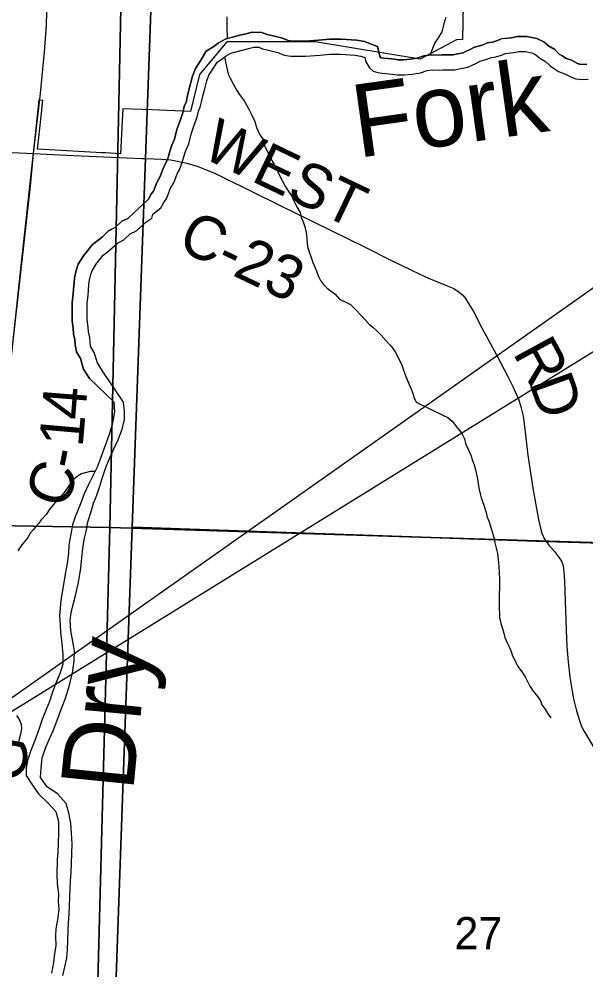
# Model space of a CAD drawing. Extents: x -7.5 to 26.5, y 3.5 to 25.5.
# Drawn here: x -2.386 to -1.65, y 20.587 to 21.822 of the extents above; entities that cross this region are included whole.
import ezdxf

# ---------------------------------------------------------------- set-up
doc = ezdxf.new("R2010")
doc.units = 0
for name, color, linetype in [('GM_X_Corporation', 7, 'Continuous'), ('GM_X_County_Road', 7, 'Continuous'), ('GM_X_County_Road_Text', 7, 'Continuous'), ('GM_X_Minor_River', 7, 'Continuous'), ('GM_X_Minor_River_Text', 7, 'Continuous'), ('GM_X_Section_Text', 7, 'Continuous'), ('GM_X_Township_Road_Text', 7, 'Continuous'), ('SH_Text', 7, 'Continuous')]:
    doc.layers.add(name, color=color, linetype=linetype)

msp = doc.modelspace()

# ---------------------------------------------------------------- linework, layer by layer
at = {"layer": 'GM_X_Corporation'}
for points in [[(-3.3166, 19.1895), (-2.696, 19.1768), (-2.693, 19.1768), (-2.3401, 19.1651), (-2.3128, 19.1642), (-2.2728, 20.2496), (-2.265, 20.4395), (-2.2643, 20.4572), (-2.2393, 21.1622), (-2.2218, 21.6412), (-2.2048, 22.1084), (-2.1854, 22.6407), (-2.1684, 23.1064), (-2.1683, 23.1094), (-2.1213, 24.4), (-5.1194, 24.4)], [(-2.1213, 24.4), (-2.1683, 23.1094), (-2.1684, 23.1064), (-2.1854, 22.6407), (-2.2048, 22.1084), (-2.2218, 21.6412), (-2.2393, 21.1622), (-1.7013, 21.1435), (-0.6673, 21.1123), (-0.2751, 21.1005), (-0.1918, 21.0972), (-0.1864, 21.0971), (-0.1806, 21.0967), (-0.0857, 21.093), (-0.0438, 21.0913), (0.0729, 21.0875), (0.2211, 21.0828)], [(-1.8079, 21.9086), (-1.8101, 21.7954), (-1.8178, 21.7951), (-1.8651, 21.77), (-2.0016, 21.7923), (-2.1161, 21.7923), (-2.1516, 21.75), (-2.1632, 21.702), (-2.2136, 21.7039), (-2.2515, 21.7053), (-2.2518, 21.6978), (-2.2541, 21.6471), (-2.2732, 21.6481), (-2.2793, 21.6484), (-2.2861, 21.6488), (-2.309, 21.65), (-2.3391, 21.6517), (-2.3623, 21.653), (-2.3601, 21.6718), (-2.357, 21.6995), (-2.3552, 21.716), (-2.3603, 21.7166), (-2.3679, 21.6477), (-2.3713, 21.6164), (-2.3726, 21.6044), (-2.3852, 21.4892), (-2.398, 21.3679)], [(0.2211, 21.0828), (0.0729, 21.0875), (-0.0438, 21.0913), (-0.0857, 21.093), (-0.1806, 21.0967), (-0.1864, 21.0971), (-0.1918, 21.0972), (-0.2751, 21.1005), (-0.6673, 21.1123), (-1.7013, 21.1435), (-2.2393, 21.1622), (-2.2643, 20.4572), (-2.265, 20.4395), (-2.2728, 20.2496), (-2.3128, 19.1642), (-2.3401, 19.1651), (-2.693, 19.1768), (-2.696, 19.1768), (-3.3166, 19.1895)]]:
    msp.add_lwpolyline(points, dxfattribs=at)
for points in [[(-3.2367, 22.18), (-2.2479, 22.1217), (-2.268, 21.1618), (-3.2602, 21.1789)], [(-2.2479, 22.1217), (-0.9461, 22.0601), (-0.9782, 21.2998), (-1.0267, 21.301), (-1.0307, 21.1237), (-1.2798, 21.1309), (-2.268, 21.1618)], [(-3.2602, 21.1789), (-2.268, 21.1618), (-2.2948, 20.1631), (-3.2852, 20.1896)], [(-2.268, 21.1618), (-1.2798, 21.1309), (-1.3089, 20.136), (-2.2948, 20.1631)]]:
    msp.add_lwpolyline(points, close=True, dxfattribs=at)
at = {"layer": 'GM_X_County_Road'}
msp.add_line((-2.4681, 21.6518), (-2.3675, 21.6474), dxfattribs=at)
for points in [[(-2.3675, 21.6474), (-2.3584, 21.7252), (-2.3531, 21.7795), (-2.3506, 21.814), (-2.3494, 21.849), (-2.3492, 21.857), (-2.3487, 21.8659), (-2.3479, 21.8755), (-2.3468, 21.8862), (-2.3416, 21.9409), (-2.3405, 21.9508), (-2.3396, 21.9573)], [(-2.5257, 20.8926), (-2.5079, 20.917), (-2.4963, 20.933), (-2.4804, 20.9556), (-2.4754, 20.9625), (-2.4713, 20.9696), (-2.4682, 20.9759), (-2.4643, 20.9845), (-2.4611, 20.9921), (-2.4572, 21.0064), (-2.4543, 21.0211), (-2.4508, 21.0481), (-2.4437, 21.0846), (-2.4394, 21.1065), (-2.4347, 21.1375), (-2.4159, 21.2518), (-2.4045, 21.3189), (-2.4008, 21.3419), (-2.3714, 21.6048), (-2.3675, 21.6474)], [(-2.3675, 21.6474), (-2.3155, 21.6446), (-2.2266, 21.6409)], [(-2.2266, 21.6409), (-2.2216, 21.6407), (-2.2012, 21.6401), (-2.1892, 21.6389), (-2.1801, 21.6374), (-2.1764, 21.6366)], [(-2.1764, 21.6366), (-2.168, 21.6347), (-2.1549, 21.6308), (-2.1419, 21.6259), (-2.1322, 21.6217), (-2.1214, 21.6167), (-2.0468, 21.5799), (-1.9363, 21.5255), (-1.9023, 21.5084), (-1.8763, 21.4957), (-1.8582, 21.4873), (-1.8488, 21.4831), (-1.8382, 21.479), (-1.8299, 21.4754), (-1.8212, 21.472), (-1.8145, 21.4674), (-1.8095, 21.4634), (-1.8059, 21.459)], [(-1.8059, 21.459), (-1.802, 21.4527), (-1.7958, 21.4422), (-1.7843, 21.42), (-1.7657, 21.3857), (-1.7505, 21.3569), (-1.7444, 21.3447), (-1.741, 21.3372), (-1.7373, 21.3289), (-1.7344, 21.3185), (-1.7313, 21.3062), (-1.7288, 21.2894), (-1.7251, 21.2556), (-1.7184, 21.213), (-1.7113, 21.1719), (-1.7087, 21.1607), (-1.7069, 21.1545), (-1.7038, 21.1474), (-1.701, 21.143), (-1.6977, 21.1386)], [(-1.6977, 21.1386), (-1.697, 21.1378), (-1.6905, 21.1305), (-1.6853, 21.1236), (-1.6814, 21.1178), (-1.6793, 21.1121), (-1.6783, 21.1035), (-1.6773, 21.0921), (-1.6755, 21.0282), (-1.6745, 21.0074), (-1.6729, 20.9871), (-1.6706, 20.9674), (-1.6677, 20.949), (-1.6658, 20.9393), (-1.6617, 20.9237), (-1.658, 20.9112), (-1.6552, 20.9032), (-1.6524, 20.8978), (-1.63, 20.8601)]]:
    msp.add_lwpolyline(points, dxfattribs=at)
at = {"layer": 'GM_X_Minor_River'}
for points in [[(-2.1151, 21.7966), (-2.1158, 21.8123), (-2.1156, 21.8191), (-2.1158, 21.8248)], [(-1.852, 21.7751), (-1.8462, 21.7899), (-1.841, 21.7977), (-1.8366, 21.8052), (-1.8341, 21.8138), (-1.8328, 21.8195), (-1.8311, 21.8243)], [(-1.7588, 21.7963), (-1.7657, 21.7936), (-1.7712, 21.792), (-1.7775, 21.7909), (-1.7845, 21.7881), (-1.7943, 21.7855), (-1.8009, 21.782), (-1.8059, 21.7798), (-1.8093, 21.7781), (-1.8184, 21.7765), (-1.8223, 21.7756), (-1.831, 21.7755), (-1.8362, 21.7753), (-1.8412, 21.7751), (-1.8501, 21.7754), (-1.8604, 21.774), (-1.8692, 21.7711), (-1.8781, 21.7696), (-1.8864, 21.7689), (-1.8936, 21.7688), (-1.8984, 21.7696), (-1.9072, 21.7706), (-1.9124, 21.7712), (-1.9159, 21.7715), (-1.916, 21.7716), (-1.9174, 21.7739), (-1.9205, 21.7864), (-1.9373, 21.7929), (-1.9474, 21.7943), (-1.9677, 21.7957), (-1.9833, 21.7958), (-1.9967, 21.7946), (-2.0146, 21.7933), (-2.0317, 21.7932), (-2.0363, 21.794), (-2.0439, 21.797), (-2.0559, 21.8), (-2.0639, 21.8018), (-2.0705, 21.8046), (-2.0835, 21.805), (-2.0912, 21.8029), (-2.0992, 21.8009), (-2.1183, 21.7958), (-2.1276, 21.7904), (-2.1345, 21.7854), (-2.1429, 21.78), (-2.1499, 21.7686), (-2.1568, 21.7579), (-2.1609, 21.7478), (-2.163, 21.7394), (-2.1642, 21.7347), (-2.1659, 21.7281), (-2.1683, 21.7185), (-2.1692, 21.7136), (-2.1715, 21.7086), (-2.1735, 21.7002), (-2.1765, 21.6916), (-2.1786, 21.6855), (-2.1813, 21.6784), (-2.1843, 21.6659), (-2.1877, 21.658), (-2.1897, 21.6516), (-2.1925, 21.6421), (-2.1955, 21.6346), (-2.1984, 21.6293), (-2.2028, 21.6174), (-2.2073, 21.6096), (-2.2114, 21.5986), (-2.2148, 21.5939), (-2.2175, 21.5885), (-2.2446, 21.5631), (-2.2525, 21.5593), (-2.2614, 21.5514), (-2.2697, 21.5469), (-2.2779, 21.5393), (-2.2839, 21.5343), (-2.2908, 21.5293), (-2.3022, 21.5145), (-2.3091, 21.5036), (-2.3118, 21.4956), (-2.314, 21.4859), (-2.3147, 21.4792), (-2.3154, 21.4715), (-2.3159, 21.4652), (-2.3171, 21.4537), (-2.3173, 21.4471), (-2.317, 21.441), (-2.3169, 21.4302), (-2.3157, 21.4205), (-2.3155, 21.4131), (-2.3137, 21.4053), (-2.3131, 21.3988), (-2.3113, 21.3896), (-2.3065, 21.381), (-2.3022, 21.3671), (-2.2946, 21.3553), (-2.2631, 21.3248)], [(-2.2631, 21.3248), (-2.2946, 21.3553), (-2.3022, 21.3671), (-2.3065, 21.381), (-2.3113, 21.3896), (-2.3131, 21.3988), (-2.3137, 21.4053), (-2.3155, 21.4131), (-2.3157, 21.4205), (-2.3169, 21.4302), (-2.317, 21.441), (-2.3173, 21.4471), (-2.3171, 21.4537), (-2.3159, 21.4652), (-2.3154, 21.4715), (-2.3147, 21.4792), (-2.314, 21.4859), (-2.3118, 21.4956), (-2.3091, 21.5036), (-2.3022, 21.5145), (-2.2908, 21.5293), (-2.2839, 21.5343), (-2.2779, 21.5393), (-2.2697, 21.5469), (-2.2614, 21.5514), (-2.2525, 21.5593), (-2.2446, 21.5631), (-2.2175, 21.5885), (-2.2148, 21.5939), (-2.2114, 21.5986), (-2.2073, 21.6096), (-2.2028, 21.6174), (-2.1984, 21.6293), (-2.1955, 21.6346), (-2.1925, 21.6421), (-2.1897, 21.6516), (-2.1877, 21.658), (-2.1843, 21.6659), (-2.1813, 21.6784), (-2.1786, 21.6855), (-2.1765, 21.6916), (-2.1735, 21.7002), (-2.1715, 21.7086), (-2.1692, 21.7136), (-2.1683, 21.7185), (-2.1659, 21.7281), (-2.1642, 21.7347), (-2.163, 21.7394), (-2.1609, 21.7478), (-2.1568, 21.7579), (-2.1499, 21.7686), (-2.1429, 21.78), (-2.1345, 21.7854), (-2.1276, 21.7904), (-2.1183, 21.7958), (-2.0992, 21.8009), (-2.0912, 21.8029), (-2.0835, 21.805), (-2.0705, 21.8046), (-2.0639, 21.8018), (-2.0559, 21.8), (-2.0439, 21.797), (-2.0363, 21.794), (-2.0317, 21.7932), (-2.0146, 21.7933), (-1.9967, 21.7946), (-1.9833, 21.7958), (-1.9677, 21.7957), (-1.9474, 21.7943), (-1.9373, 21.7929), (-1.9205, 21.7864), (-1.9174, 21.7739), (-1.916, 21.7716), (-1.9159, 21.7715), (-1.9124, 21.7712), (-1.9072, 21.7706), (-1.8984, 21.7696), (-1.8936, 21.7688), (-1.8864, 21.7689), (-1.8781, 21.7696), (-1.8692, 21.7711), (-1.8604, 21.774), (-1.8501, 21.7754), (-1.8412, 21.7751), (-1.8362, 21.7753), (-1.831, 21.7755), (-1.8223, 21.7756), (-1.8184, 21.7765), (-1.8093, 21.7781), (-1.8059, 21.7798), (-1.8009, 21.782), (-1.7943, 21.7855), (-1.7845, 21.7881), (-1.7775, 21.7909), (-1.7712, 21.792), (-1.7657, 21.7936), (-1.7612, 21.7953)], [(-1.6484, 21.7633), (-1.6537, 21.7629), (-1.658, 21.7634), (-1.6604, 21.7643), (-1.6682, 21.7684), (-1.6761, 21.7713), (-1.6798, 21.7738), (-1.6843, 21.7765), (-1.6901, 21.7823), (-1.6982, 21.7873), (-1.7045, 21.7922), (-1.7133, 21.7966), (-1.7262, 21.7993), (-1.7384, 21.7991), (-1.7466, 21.7977), (-1.7588, 21.7963)], [(-1.7563, 21.7966), (-1.7466, 21.7977), (-1.7384, 21.7991), (-1.7262, 21.7993), (-1.7133, 21.7966), (-1.7045, 21.7922), (-1.6982, 21.7873), (-1.6901, 21.7823), (-1.6843, 21.7765), (-1.6798, 21.7738), (-1.6761, 21.7713), (-1.6682, 21.7684), (-1.6604, 21.7643), (-1.658, 21.7634), (-1.6537, 21.7629), (-1.6484, 21.7633)], [(-2.2506, 21.3244), (-2.2781, 21.3657), (-2.2843, 21.3754), (-2.2885, 21.3888), (-2.2928, 21.3965), (-2.2938, 21.4015), (-2.2943, 21.4083), (-2.296, 21.4156), (-2.2962, 21.422), (-2.2975, 21.4316), (-2.2975, 21.4414), (-2.2977, 21.4471), (-2.2976, 21.4524), (-2.2965, 21.4634), (-2.2959, 21.4698), (-2.2953, 21.4774), (-2.2948, 21.4827), (-2.293, 21.4903), (-2.2913, 21.4951), (-2.2862, 21.5033), (-2.277, 21.5152), (-2.272, 21.5188), (-2.265, 21.5247), (-2.2583, 21.5309), (-2.2502, 21.5352), (-2.2416, 21.5429), (-2.2334, 21.5469), (-2.2213, 21.5582), (-2.2135, 21.5633), (-2.2122, 21.5686), (-2.2017, 21.5766), (-2.1981, 21.5837), (-2.1941, 21.5893), (-2.1896, 21.6013), (-2.1851, 21.6091), (-2.1806, 21.6211), (-2.1778, 21.6263), (-2.174, 21.6357), (-2.1711, 21.6459), (-2.1694, 21.6511), (-2.1657, 21.6598), (-2.1627, 21.6726), (-2.1602, 21.6789), (-2.1581, 21.6853), (-2.1548, 21.6947), (-2.153, 21.7023), (-2.1506, 21.7075), (-2.1492, 21.7143), (-2.147, 21.7233), (-2.1453, 21.7297), (-2.144, 21.7346), (-2.1423, 21.7418), (-2.1394, 21.7489), (-2.1334, 21.7582), (-2.1286, 21.766), (-2.1236, 21.7693), (-2.117, 21.774), (-2.1108, 21.7776), (-2.0943, 21.782), (-2.0862, 21.7841), (-2.0812, 21.7854), (-2.0748, 21.7852), (-2.0699, 21.7832), (-2.0604, 21.781), (-2.0498, 21.7784), (-2.0416, 21.7751), (-2.0332, 21.7737), (-2.0138, 21.7738), (-1.9951, 21.7752), (-1.9825, 21.7763), (-1.9684, 21.7762), (-1.9494, 21.7749), (-1.9422, 21.7739), (-1.937, 21.7718), (-1.9356, 21.7665), (-1.9309, 21.7584), (-1.9261, 21.7544), (-1.92, 21.7523), (-1.9144, 21.7518), (-1.9094, 21.7512), (-1.9011, 21.7502), (-1.895, 21.7493), (-1.8855, 21.7494), (-1.8756, 21.7502), (-1.8645, 21.7521), (-1.856, 21.7549), (-1.8491, 21.7558), (-1.8411, 21.7556), (-1.8354, 21.7558), (-1.8305, 21.756), (-1.8198, 21.7561), (-1.8144, 21.7574), (-1.803, 21.7593), (-1.7976, 21.7622), (-1.7925, 21.7643), (-1.7871, 21.7672), (-1.7783, 21.7696), (-1.7721, 21.772), (-1.7668, 21.773), (-1.7595, 21.7751), (-1.7541, 21.7772)], [(-2.1191, 21.7725), (-2.1143, 21.7504), (-2.1114, 21.7442), (-2.1078, 21.7377), (-2.1046, 21.7311), (-2.1009, 21.7257), (-2.0936, 21.7156), (-2.0903, 21.7098), (-2.0875, 21.7048), (-2.0835, 21.6971), (-2.0799, 21.689), (-2.0775, 21.6813), (-2.0732, 21.6717), (-2.0696, 21.6663), (-2.069, 21.6613), (-2.0643, 21.6513), (-2.06, 21.6436), (-2.0571, 21.6374), (-2.0528, 21.6301), (-2.0467, 21.617), (-2.0438, 21.6116), (-2.0402, 21.605), (-2.0362, 21.598), (-2.0319, 21.5918), (-2.0297, 21.5868), (-2.0254, 21.578), (-2.0211, 21.5706), (-2.0194, 21.5645), (-2.0169, 21.5584), (-2.0148, 21.5522), (-2.0131, 21.5446), (-2.0122, 21.537), (-2.0116, 21.5305), (-2.011, 21.5248), (-2.0093, 21.5198), (-2.0065, 21.5121), (-2.0044, 21.506), (-2.0012, 21.4987), (-1.9994, 21.4937), (-1.9969, 21.4875), (-1.9944, 21.4825), (-1.9904, 21.4771), (-1.9856, 21.4724), (-1.9756, 21.4645), (-1.9696, 21.4582), (-1.9614, 21.4545), (-1.9554, 21.4513), (-1.9484, 21.4443), (-1.9425, 21.438), (-1.9366, 21.4314), (-1.9314, 21.4259), (-1.9266, 21.422), (-1.9207, 21.4165), (-1.9155, 21.4114), (-1.9092, 21.4043), (-1.9044, 21.3989), (-1.9, 21.3938), (-1.8968, 21.3884), (-1.8928, 21.3803), (-1.8892, 21.3737), (-1.8871, 21.3672), (-1.8843, 21.3599), (-1.8793, 21.3476), (-1.8768, 21.3418), (-1.8744, 21.3357), (-1.8726, 21.3299), (-1.8701, 21.3246)], [(-1.7541, 21.7772), (-1.7438, 21.7784), (-1.7365, 21.7797), (-1.7281, 21.7798), (-1.7198, 21.778), (-1.7149, 21.7756), (-1.7093, 21.7712), (-1.7022, 21.7668), (-1.6963, 21.761), (-1.6903, 21.7574), (-1.6851, 21.7538), (-1.6761, 21.7505), (-1.6682, 21.7464), (-1.6626, 21.7444), (-1.6542, 21.7433), (-1.6466, 21.7439)], [(-2.2631, 21.3248), (-2.2623, 21.3118), (-2.2649, 21.2975), (-2.2687, 21.2839), (-2.2728, 21.2715), (-2.2809, 21.2505), (-2.2846, 21.2399), (-2.291, 21.2272), (-2.2958, 21.2174), (-2.3014, 21.2054), (-2.3071, 21.1904), (-2.3131, 21.1754), (-2.3168, 21.1652), (-2.319, 21.1531), (-2.3213, 21.1392), (-2.3219, 21.1285), (-2.3234, 21.1149), (-2.326, 21.1013), (-2.3301, 21.0775), (-2.3319, 21.0673), (-2.3329, 21.0571), (-2.3335, 21.0473), (-2.3327, 21.0351), (-2.3322, 21.0256), (-2.3307, 21.0107), (-2.3291, 20.997), (-2.3294, 20.9842), (-2.3328, 20.9732), (-2.3384, 20.9597), (-2.3433, 20.9466), (-2.3466, 20.936), (-2.3507, 20.9255), (-2.3559, 20.9123), (-2.36, 20.9007), (-2.3649, 20.8871), (-2.3706, 20.8721), (-2.3751, 20.8593), (-2.3769, 20.8491), (-2.3768, 20.8396), (-2.3676, 20.8257), (-2.3607, 20.8161), (-2.3489, 20.804), (-2.3385, 20.7931), (-2.3347, 20.7801), (-2.3347, 20.7657), (-2.3351, 20.752), (-2.3357, 20.7403), (-2.3364, 20.7308), (-2.3369, 20.7115), (-2.3364, 20.6989), (-2.3349, 20.686), (-2.3351, 20.6761), (-2.3346, 20.6655), (-2.3361, 20.6523), (-2.3383, 20.6405), (-2.3389, 20.6311), (-2.3385, 20.6185), (-2.3399, 20.6087), (-2.3413, 20.597), (-2.344, 20.583)], [(-1.8701, 21.3246), (-1.8347, 21.3073), (-1.8291, 21.3044), (-1.8232, 21.2996), (-1.8159, 21.2903), (-1.8112, 21.2848), (-1.8076, 21.2767), (-1.8059, 21.2709), (-1.8028, 21.2636), (-1.7993, 21.2555), (-1.7972, 21.2489), (-1.7948, 21.2432), (-1.7931, 21.2366), (-1.7911, 21.2271), (-1.7895, 21.219), (-1.7886, 21.2129), (-1.7869, 21.2056), (-1.7856, 21.2003), (-1.7821, 21.1907), (-1.7794, 21.1811), (-1.7781, 21.1753), (-1.7753, 21.1691), (-1.7739, 21.1649), (-1.7688, 21.1476), (-1.7679, 21.1419), (-1.7665, 21.1365), (-1.7646, 21.1281), (-1.7637, 21.1201), (-1.7631, 21.1155), (-1.7629, 21.1109), (-1.7624, 21.1026), (-1.7619, 21.0957), (-1.7617, 21.0908), (-1.7625, 21.0672), (-1.7623, 21.0611), (-1.7625, 21.0566), (-1.762, 21.0497), (-1.7617, 21.0448), (-1.7601, 21.0371), (-1.7581, 21.0306), (-1.7564, 21.0244), (-1.755, 21.0191), (-1.7519, 21.0121), (-1.7483, 21.0052), (-1.7466, 21.0009), (-1.7449, 20.9952), (-1.7406, 20.9867), (-1.7381, 20.9813), (-1.7323, 20.9738), (-1.728, 20.9668), (-1.7223, 20.9556), (-1.718, 20.949), (-1.7122, 20.942), (-1.7085, 20.9365), (-1.7068, 20.9315), (-1.7028, 20.9264), (-1.6989, 20.9195), (-1.6953, 20.9144)], [(-2.3293, 20.58), (-2.3263, 20.5932), (-2.3241, 20.603), (-2.3231, 20.6132), (-2.3224, 20.6386), (-2.3218, 20.6485), (-2.3211, 20.6602), (-2.3205, 20.6701), (-2.3202, 20.6822), (-2.3195, 20.6924), (-2.3193, 20.7031), (-2.3186, 20.7137), (-2.3179, 20.7262), (-2.3176, 20.7379), (-2.3169, 20.7508), (-2.3181, 20.7649), (-2.3189, 20.7778), (-2.3216, 20.7908), (-2.325, 20.8034), (-2.3361, 20.8158), (-2.3495, 20.8249), (-2.3582, 20.8373), (-2.3576, 20.8494), (-2.3561, 20.8626), (-2.3512, 20.8765), (-2.3467, 20.8871), (-2.3419, 20.8979), (-2.337, 20.9103), (-2.3309, 20.9269), (-2.3261, 20.9389), (-2.3219, 20.9525), (-2.3194, 20.9623), (-2.3164, 20.9755), (-2.3146, 20.9887), (-2.3142, 21.0016), (-2.3162, 21.0138), (-2.3188, 21.0279), (-2.3196, 21.0412), (-2.3183, 21.051), (-2.3157, 21.0616), (-2.3128, 21.0733), (-2.3093, 21.0884), (-2.3076, 21.0982), (-2.3058, 21.1088), (-2.3047, 21.1224), (-2.3032, 21.1345), (-2.3014, 21.1462), (-2.2984, 21.1583), (-2.2966, 21.1689), (-2.2921, 21.1836), (-2.2892, 21.1934), (-2.2851, 21.2039), (-2.2811, 21.2152), (-2.2781, 21.2253), (-2.2728, 21.2408), (-2.2679, 21.2532), (-2.2631, 21.2637), (-2.2575, 21.2757), (-2.2522, 21.2892), (-2.2493, 21.302), (-2.249, 21.3115), (-2.2506, 21.3244)], [(-2.2873, 21.2344), (-2.2939, 21.2343), (-2.305, 21.2316), (-2.3101, 21.2283), (-2.3159, 21.2236), (-2.3243, 21.2114), (-2.3275, 21.2073), (-2.3311, 21.2032), (-2.335, 21.1984), (-2.341, 21.1918), (-2.3461, 21.1859), (-2.3509, 21.1788), (-2.3572, 21.1715), (-2.3604, 21.1674), (-2.364, 21.1633), (-2.3675, 21.1589), (-2.3715, 21.1545), (-2.3751, 21.1478), (-2.3823, 21.1393), (-2.3878, 21.1315)], [(-2.3896, 20.9176), (-2.3859, 20.9125), (-2.3835, 20.9063), (-2.3829, 20.9002), (-2.3848, 20.8916), (-2.3861, 20.887), (-2.3874, 20.8806)]]:
    msp.add_lwpolyline(points, dxfattribs=at)
at = {"layer": 'SH_Text'}
msp.add_lwpolyline([(2.4449, 24.351), (-2.5961, 20.7995), (2.4449, 23.9163)], close=True, dxfattribs=at)

# ---------------------------------------------------------------- texts
at = {"layer": 'GM_X_County_Road_Text'}
for s, height, rotation, p in [('WEST', 0.05682, 334.4507, (-2.1508, 21.6433)), ('C-23', 0.05682, 334.5079, (-2.1825, 21.5242)), ('R', 0.0568, 298.6002, (-1.7454, 21.3886)), ('D', 0.0568, 289.8261, (-1.724, 21.3497)), ('4', 0.0568, 85.4878, (-2.3005, 21.3004)), ('1', 0.0568, 85.0012, (-2.3036, 21.265)), ('-', 0.0568, 78.5929, (-2.3092, 21.2353)), ('C', 0.0568, 72.4269, (-2.3249, 21.1843))]:
    msp.add_text(s, height=height, rotation=rotation, dxfattribs=at).set_placement(p)
at = {"layer": 'GM_X_Minor_River_Text'}
for s, height, rotation, p in [('Fork', 0.0947, 7.9854, (-1.9461, 21.6415)), ('Dry', 0.09471, 84.3173, (-2.238, 20.8178))]:
    msp.add_text(s, height=height, rotation=rotation, dxfattribs=at).set_placement(p)
at = {"layer": 'GM_X_Section_Text'}
msp.add_text('27', height=0.04186, rotation=0, dxfattribs=at).set_placement((-1.8205, 20.6141))
at = {"layer": 'GM_X_Township_Road_Text'}
msp.add_text('G', height=0.0568, rotation=78.9615, dxfattribs=at).set_placement((-2.3823, 20.8284))

doc.saveas('drawing.dxf')
